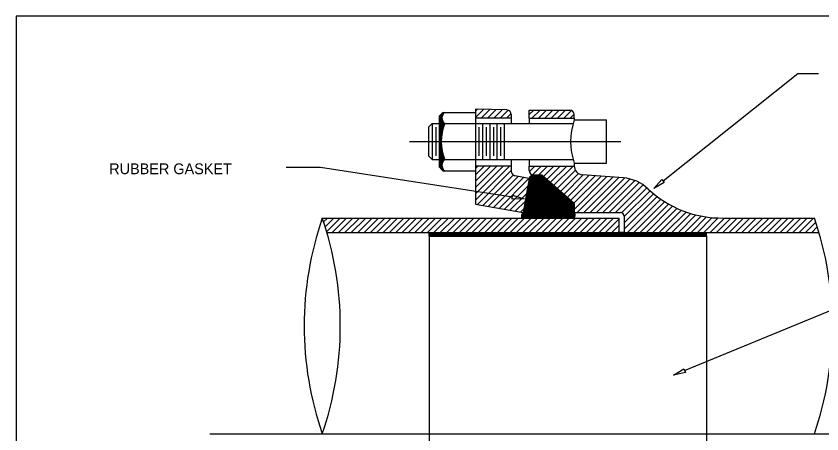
# Model space of a CAD drawing. Extents: x 2147138 to 2147698, y 2147153 to 2147515.
# Drawn here: x 2147558.3 to 2147647.9, y 2147297.7 to 2147344.1 of the extents above; entities that cross this region are included whole.
import ezdxf

# ---------------------------------------------------------------- set-up
doc = ezdxf.new("R2010")
doc.units = 0
for name, color, linetype in [('EQPM', 7, 'Continuous'), ('G-ANNO-TEXT-LW10', 7, 'Continuous'), ('G-DETL-CNTR', 7, 'Continuous'), ('G-DETL-LW10', 7, 'Continuous'), ('G-DETL-PATT', 7, 'Continuous'), ('PATTERN_CLASS', 7, 'Continuous')]:
    doc.layers.add(name, color=color, linetype=linetype)

msp = doc.modelspace()

# ---------------------------------------------------------------- linework, layer by layer
at = {"layer": 'EQPM'}
for p, q in [((2147604.195, 2147319.672), (2147604.195, 2147320.072)), ((2147604.195, 2147320.042), (2147635.045, 2147320.042)), ((2147604.195, 2147319.992), (2147635.045, 2147319.992)), ((2147604.195, 2147319.942), (2147635.045, 2147319.942)), ((2147604.195, 2147319.892), (2147635.045, 2147319.892)), ((2147604.195, 2147319.842), (2147635.045, 2147319.842)), ((2147604.195, 2147319.792), (2147635.045, 2147319.792)), ((2147604.195, 2147319.742), (2147635.045, 2147319.742)), ((2147604.195, 2147319.692), (2147635.045, 2147319.692)), ((2147604.195, 2147319.672), (2147635.045, 2147319.672)), ((2147625.93, 2147320.072), (2147625.33, 2147320.072)), ((2147635.045, 2147319.672), (2147635.045, 2147320.072))]:
    msp.add_line(p, q, dxfattribs=at)
at = {"layer": 'G-ANNO-TEXT-LW10'}
for p, q in [((2147630.207, 2147325.797), (2147645.187, 2147337.726)), ((2147645.187, 2147337.726), (2147647.51, 2147337.726)), ((2147592.12, 2147327.285), (2147588.288, 2147327.285)), ((2147613.444, 2147324.007), (2147592.12, 2147327.285)), ((2147632.604, 2147304.708), (2147649.105, 2147311.508))]:
    msp.add_line(p, q, dxfattribs=at)
for points in [[(2147630.346, 2147325.623), (2147629.163, 2147324.965), (2147630.069, 2147325.971)], [(2147613.478, 2147324.227), (2147614.764, 2147323.805), (2147613.41, 2147323.788)], [(2147632.688, 2147304.502), (2147631.369, 2147304.199), (2147632.519, 2147304.914)]]:
    msp.add_lwpolyline(points, close=True, dxfattribs=at)
at = {"layer": 'G-DETL-CNTR'}
for p, q in [((2147601.998, 2147330.172), (2147625.503, 2147330.172)), ((2147579.795, 2147297.672), (2147660.381, 2147297.672))]:
    msp.add_line(p, q, dxfattribs=at)
at = {"layer": 'G-DETL-LW10'}
for p, q in [((2147605.33, 2147333.022), (2147605.73, 2147333.422)), ((2147605.73, 2147333.422), (2147609.33, 2147333.422)), ((2147612.845, 2147333.687), (2147609.33, 2147333.792)), ((2147609.33, 2147333.792), (2147609.33, 2147332.772)), ((2147609.33, 2147333.422), (2147609.33, 2147326.922)), ((2147613.33, 2147333.187), (2147613.33, 2147332.772)), ((2147615.33, 2147333.672), (2147619.83, 2147333.672)), ((2147615.33, 2147332.772), (2147615.33, 2147333.672)), ((2147620.33, 2147332.772), (2147620.33, 2147333.172)), ((2147605.33, 2147333.022), (2147605.33, 2147327.322)), ((2147613.33, 2147332.772), (2147609.33, 2147332.772)), ((2147613.33, 2147332.772), (2147613.33, 2147332.172)), ((2147615.33, 2147332.772), (2147620.33, 2147332.772)), ((2147615.33, 2147332.772), (2147615.33, 2147332.172)), ((2147620.33, 2147332.772), (2147620.33, 2147332.572)), ((2147620.33, 2147332.572), (2147623.93, 2147332.572)), ((2147623.93, 2147327.772), (2147623.93, 2147332.572)), ((2147604.53, 2147332.172), (2147604.13, 2147331.772)), ((2147604.13, 2147331.772), (2147604.13, 2147328.572)), ((2147604.53, 2147332.172), (2147604.53, 2147328.172)), ((2147604.53, 2147332.172), (2147605.33, 2147332.172)), ((2147604.93, 2147331.772), (2147604.93, 2147328.572)), ((2147605.93, 2147332.172), (2147609.33, 2147332.172)), ((2147609.33, 2147332.172), (2147620.206, 2147332.172)), ((2147609.73, 2147331.772), (2147609.73, 2147328.572)), ((2147610.13, 2147332.172), (2147610.13, 2147328.172)), ((2147610.53, 2147331.772), (2147610.53, 2147328.572)), ((2147610.93, 2147332.172), (2147610.93, 2147328.172)), ((2147611.33, 2147331.772), (2147611.33, 2147328.572)), ((2147611.73, 2147332.172), (2147611.73, 2147328.172)), ((2147612.13, 2147331.772), (2147612.13, 2147328.572)), ((2147612.53, 2147332.172), (2147612.53, 2147328.172)), ((2147604.13, 2147328.572), (2147604.53, 2147328.172)), ((2147604.53, 2147328.172), (2147605.33, 2147328.172)), ((2147605.93, 2147328.172), (2147609.33, 2147328.172)), ((2147609.33, 2147328.172), (2147620.206, 2147328.172)), ((2147613.33, 2147328.172), (2147613.33, 2147327.452)), ((2147615.33, 2147328.052), (2147615.33, 2147327.452)), ((2147620.33, 2147327.772), (2147623.93, 2147327.772)), ((2147620.33, 2147327.772), (2147620.33, 2147327.477)), ((2147605.33, 2147327.322), (2147605.73, 2147326.922)), ((2147605.73, 2147326.922), (2147609.33, 2147326.922)), ((2147609.33, 2147327.452), (2147609.33, 2147323.21)), ((2147613.33, 2147327.452), (2147609.33, 2147327.452)), ((2147613.33, 2147327.452), (2147613.33, 2147326.862)), ((2147615.33, 2147327.452), (2147620.33, 2147327.452)), ((2147615.33, 2147326.952), (2147615.33, 2147327.452)), ((2147615.33, 2147326.052), (2147613.732, 2147326.372)), ((2147615.33, 2147326.052), (2147614.663, 2147322.27)), ((2147615.357, 2147326.069), (2147614.671, 2147322.245)), ((2147615.334, 2147326.18), (2147615.314, 2147326.12)), ((2147615.314, 2147326.12), (2147615.314, 2147326.077)), ((2147615.314, 2147326.077), (2147615.357, 2147326.069)), ((2147615.373, 2147326.247), (2147615.334, 2147326.18)), ((2147615.456, 2147326.318), (2147615.373, 2147326.247)), ((2147615.559, 2147326.381), (2147615.456, 2147326.318)), ((2147615.642, 2147326.417), (2147615.559, 2147326.381)), ((2147615.717, 2147326.437), (2147615.642, 2147326.417)), ((2147616.725, 2147326.438), (2147615.717, 2147326.437)), ((2147615.83, 2147326.452), (2147616.73, 2147326.452)), ((2147620.305, 2147323.261), (2147616.725, 2147326.438)), ((2147620.33, 2147323.272), (2147616.73, 2147326.452)), ((2147625.793, 2147326.138), (2147621.252, 2147326.48)), ((2147620.304, 2147322.261), (2147620.305, 2147323.261)), ((2147620.33, 2147323.272), (2147620.33, 2147322.272)), ((2147609.33, 2147323.21), (2147614.663, 2147322.27)), ((2147592.302, 2147321.672), (2147625.33, 2147321.672)), ((2147614.466, 2147321.878), (2147614.459, 2147321.824)), ((2147614.459, 2147321.824), (2147614.459, 2147321.786)), ((2147614.459, 2147321.786), (2147614.464, 2147321.764)), ((2147614.464, 2147321.764), (2147614.478, 2147321.751)), ((2147614.479, 2147321.985), (2147614.466, 2147321.878)), ((2147614.478, 2147321.751), (2147614.498, 2147321.748)), ((2147614.504, 2147322.066), (2147614.479, 2147321.985)), ((2147614.498, 2147321.748), (2147614.519, 2147321.747)), ((2147614.539, 2147322.143), (2147614.504, 2147322.066)), ((2147614.519, 2147321.747), (2147620.341, 2147321.747)), ((2147614.59, 2147322.202), (2147614.539, 2147322.143)), ((2147614.628, 2147322.232), (2147614.59, 2147322.202)), ((2147614.671, 2147322.245), (2147614.628, 2147322.232)), ((2147620.39, 2147322.165), (2147620.304, 2147322.261)), ((2147620.33, 2147322.272), (2147625.43, 2147322.272)), ((2147620.341, 2147321.747), (2147620.395, 2147321.825)), ((2147620.422, 2147322.084), (2147620.39, 2147322.165)), ((2147620.395, 2147321.825), (2147620.431, 2147321.956)), ((2147620.431, 2147321.956), (2147620.422, 2147322.084)), ((2147625.33, 2147320.072), (2147625.33, 2147321.672)), ((2147625.93, 2147320.072), (2147625.93, 2147321.772)), ((2147636.86, 2147321.672), (2147647.038, 2147321.672)), ((2147592.813, 2147320.072), (2147625.33, 2147320.072)), ((2147625.93, 2147320.072), (2147647.548, 2147320.072))]:
    msp.add_line(p, q, dxfattribs=at)
for centre, radius, start, end in [((2147606.401, 2147332.797), 0.783, 127.00306, 232.99694), ((2147612.83, 2147333.187), 0.5, 0, 88.28164), ((2147619.83, 2147333.172), 0.5, 0, 90), ((2147627.33, 2147330.172), 7.4, 161.07536, 198.92464), ((2147610.73, 2147330.172), 5.2, 157.38014, 202.61986), ((2147606.401, 2147327.547), 0.783, 127.00306, 232.99694), ((2147613.83, 2147326.862), 0.5, 180, 258.69007), ((2147615.83, 2147326.952), 0.5, 180, 270), ((2147621.33, 2147327.477), 1, 180, 265.5072), ((2147625.43, 2147321.652), 4.5, 46.15465, 85.38171), ((2147636.69, 2147333.558), 11.886, 226.76421, 270.82117), ((2147627.142, 2147309.672), 36.849, 160.99467, 199.00533), ((2147627.142, 2147309.672), 36.849, 160.99467, 199.00533), ((2147557.462, 2147309.672), 36.849, 340.99467, 19.00533), ((2147625.43, 2147321.772), 0.5, 0, 90), ((2147612.198, 2147309.672), 36.849, 340.99467, 19.00533)]:
    msp.add_arc(centre, radius, start, end, dxfattribs=at)
at = {"layer": 'G-DETL-PATT'}
for p, q in [((2147605.45, 2147330.172), (2147605.45, 2147333.142)), ((2147605.5, 2147330.172), (2147605.5, 2147333.192)), ((2147605.55, 2147330.625), (2147605.55, 2147333.242)), ((2147605.6, 2147331.021), (2147605.6, 2147333.292)), ((2147605.65, 2147333.017), (2147605.65, 2147333.342)), ((2147605.7, 2147333.145), (2147605.7, 2147333.392)), ((2147605.75, 2147333.231), (2147605.75, 2147333.422)), ((2147605.8, 2147333.298), (2147605.8, 2147333.422)), ((2147605.85, 2147333.353), (2147605.85, 2147333.422)), ((2147605.9, 2147333.398), (2147605.9, 2147333.422)), ((2147609.33, 2147333.546), (2147609.569, 2147333.785)), ((2147609.33, 2147332.839), (2147610.256, 2147333.765)), ((2147609.971, 2147332.772), (2147610.942, 2147333.744)), ((2147610.678, 2147332.772), (2147611.629, 2147333.723)), ((2147611.385, 2147332.772), (2147612.315, 2147333.703)), ((2147612.092, 2147332.772), (2147612.983, 2147333.663)), ((2147612.799, 2147332.772), (2147613.319, 2147333.292)), ((2147615.33, 2147333.182), (2147615.82, 2147333.672)), ((2147615.627, 2147332.772), (2147616.527, 2147333.672)), ((2147616.335, 2147332.772), (2147617.235, 2147333.672)), ((2147617.042, 2147332.772), (2147617.942, 2147333.672)), ((2147617.749, 2147332.772), (2147618.649, 2147333.672)), ((2147618.456, 2147332.772), (2147619.356, 2147333.672)), ((2147619.163, 2147332.772), (2147620.024, 2147333.633)), ((2147619.87, 2147332.772), (2147620.327, 2147333.229)), ((2147605.35, 2147330.172), (2147605.35, 2147333.042)), ((2147605.4, 2147330.172), (2147605.4, 2147333.092)), ((2147605.65, 2147331.282), (2147605.65, 2147332.578)), ((2147605.7, 2147331.49), (2147605.7, 2147332.45)), ((2147605.75, 2147331.668), (2147605.75, 2147332.363)), ((2147605.8, 2147331.825), (2147605.8, 2147332.296)), ((2147605.85, 2147331.968), (2147605.85, 2147332.242)), ((2147605.9, 2147332.098), (2147605.9, 2147332.196)), ((2147605.35, 2147327.303), (2147605.35, 2147330.172)), ((2147605.4, 2147327.253), (2147605.4, 2147330.172)), ((2147605.45, 2147327.203), (2147605.45, 2147330.172)), ((2147605.5, 2147327.153), (2147605.5, 2147330.172)), ((2147605.55, 2147327.103), (2147605.55, 2147329.72)), ((2147605.6, 2147327.053), (2147605.6, 2147329.324)), ((2147605.65, 2147327.767), (2147605.65, 2147329.063)), ((2147605.7, 2147327.895), (2147605.7, 2147328.855)), ((2147605.75, 2147327.981), (2147605.75, 2147328.677)), ((2147605.8, 2147328.048), (2147605.8, 2147328.519)), ((2147605.85, 2147328.103), (2147605.85, 2147328.377)), ((2147605.9, 2147328.148), (2147605.9, 2147328.247)), ((2147605.65, 2147327.003), (2147605.65, 2147327.328)), ((2147605.7, 2147326.953), (2147605.7, 2147327.2)), ((2147605.75, 2147326.922), (2147605.75, 2147327.113)), ((2147605.8, 2147326.922), (2147605.8, 2147327.046)), ((2147605.85, 2147326.922), (2147605.85, 2147326.992)), ((2147605.9, 2147326.922), (2147605.9, 2147326.946)), ((2147609.33, 2147327.182), (2147609.6, 2147327.452)), ((2147609.33, 2147326.475), (2147610.307, 2147327.452)), ((2147609.33, 2147325.768), (2147611.015, 2147327.452)), ((2147609.33, 2147325.061), (2147611.722, 2147327.452)), ((2147609.33, 2147324.354), (2147612.429, 2147327.452)), ((2147609.33, 2147323.647), (2147613.136, 2147327.452)), ((2147609.56, 2147323.17), (2147613.33, 2147326.94)), ((2147615.342, 2147326.843), (2147615.952, 2147327.452)), ((2147615.682, 2147326.475), (2147616.659, 2147327.452)), ((2147616.366, 2147326.452), (2147617.366, 2147327.452)), ((2147616.912, 2147326.292), (2147618.073, 2147327.452)), ((2147617.288, 2147325.96), (2147618.78, 2147327.452)), ((2147617.663, 2147325.628), (2147619.488, 2147327.452)), ((2147618.039, 2147325.297), (2147620.195, 2147327.452)), ((2147618.414, 2147324.965), (2147620.451, 2147327.001)), ((2147610.161, 2147323.064), (2147613.548, 2147326.45)), ((2147610.762, 2147322.958), (2147614.103, 2147326.298)), ((2147611.363, 2147322.852), (2147614.692, 2147326.18)), ((2147611.965, 2147322.746), (2147615.281, 2147326.062)), ((2147615.375, 2147321.747), (2147615.375, 2147326.249)), ((2147615.5, 2147321.747), (2147615.5, 2147326.345)), ((2147615.625, 2147321.747), (2147615.625, 2147326.41)), ((2147615.75, 2147321.747), (2147615.75, 2147326.437)), ((2147615.875, 2147321.747), (2147615.875, 2147326.437)), ((2147616, 2147321.747), (2147616, 2147326.437)), ((2147616.125, 2147321.747), (2147616.125, 2147326.437)), ((2147616.25, 2147321.747), (2147616.25, 2147326.437)), ((2147616.375, 2147321.747), (2147616.375, 2147326.437)), ((2147616.5, 2147321.747), (2147616.5, 2147326.437)), ((2147616.625, 2147321.747), (2147616.625, 2147326.437)), ((2147616.75, 2147321.747), (2147616.75, 2147326.416)), ((2147616.875, 2147321.747), (2147616.875, 2147326.305)), ((2147617, 2147321.747), (2147617, 2147326.194)), ((2147617.125, 2147321.747), (2147617.125, 2147326.083)), ((2147617.25, 2147321.747), (2147617.25, 2147325.972)), ((2147618.79, 2147324.633), (2147620.791, 2147326.635)), ((2147619.165, 2147324.302), (2147621.337, 2147326.474)), ((2147619.541, 2147323.97), (2147621.995, 2147326.424)), ((2147619.916, 2147323.638), (2147622.652, 2147326.374)), ((2147620.292, 2147323.307), (2147623.31, 2147326.325)), ((2147620.33, 2147322.638), (2147623.967, 2147326.275)), ((2147620.671, 2147322.272), (2147624.625, 2147326.226)), ((2147621.379, 2147322.272), (2147625.282, 2147326.176)), ((2147622.086, 2147322.272), (2147625.937, 2147326.124)), ((2147622.793, 2147322.272), (2147626.535, 2147326.015)), ((2147612.566, 2147322.64), (2147615.191, 2147325.265)), ((2147615.25, 2147321.747), (2147615.25, 2147325.471)), ((2147617.375, 2147321.747), (2147617.375, 2147325.861)), ((2147617.5, 2147321.747), (2147617.5, 2147325.75)), ((2147617.625, 2147321.747), (2147617.625, 2147325.639)), ((2147617.75, 2147321.747), (2147617.75, 2147325.528)), ((2147617.875, 2147321.747), (2147617.875, 2147325.417)), ((2147618, 2147321.747), (2147618, 2147325.306)), ((2147618.125, 2147321.747), (2147618.125, 2147325.196)), ((2147618.25, 2147321.747), (2147618.25, 2147325.085)), ((2147623.5, 2147322.272), (2147627.07, 2147325.843)), ((2147624.207, 2147322.272), (2147627.554, 2147325.62)), ((2147624.914, 2147322.272), (2147627.993, 2147325.351)), ((2147613.167, 2147322.534), (2147615.04, 2147324.407)), ((2147615.125, 2147321.747), (2147615.125, 2147324.775)), ((2147618.375, 2147321.747), (2147618.375, 2147324.974)), ((2147618.5, 2147321.747), (2147618.5, 2147324.863)), ((2147618.625, 2147321.747), (2147618.625, 2147324.752)), ((2147618.75, 2147321.747), (2147618.75, 2147324.641)), ((2147618.875, 2147321.747), (2147618.875, 2147324.53)), ((2147619, 2147321.747), (2147619, 2147324.419)), ((2147619.125, 2147321.747), (2147619.125, 2147324.308)), ((2147619.25, 2147321.747), (2147619.25, 2147324.197)), ((2147625.594, 2147322.245), (2147628.39, 2147325.042)), ((2147625.922, 2147321.866), (2147628.759, 2147324.703)), ((2147625.93, 2147321.167), (2147629.14, 2147324.377)), ((2147613.768, 2147322.428), (2147614.889, 2147323.548)), ((2147614.875, 2147321.747), (2147614.875, 2147323.382)), ((2147615, 2147321.747), (2147615, 2147324.078)), ((2147619.375, 2147321.747), (2147619.375, 2147324.086)), ((2147619.5, 2147321.747), (2147619.5, 2147323.975)), ((2147619.625, 2147321.747), (2147619.625, 2147323.864)), ((2147619.75, 2147321.747), (2147619.75, 2147323.754)), ((2147619.875, 2147321.747), (2147619.875, 2147323.643)), ((2147620, 2147321.747), (2147620, 2147323.532)), ((2147620.125, 2147321.747), (2147620.125, 2147323.421)), ((2147620.25, 2147321.747), (2147620.25, 2147323.31)), ((2147625.93, 2147320.46), (2147629.535, 2147324.065)), ((2147626.25, 2147320.072), (2147629.946, 2147323.769)), ((2147626.957, 2147320.072), (2147630.373, 2147323.489)), ((2147614.369, 2147322.322), (2147614.737, 2147322.69)), ((2147614.75, 2147321.747), (2147614.75, 2147322.685)), ((2147627.664, 2147320.072), (2147630.816, 2147323.224)), ((2147628.371, 2147320.072), (2147631.275, 2147322.976)), ((2147629.078, 2147320.072), (2147631.751, 2147322.746)), ((2147629.785, 2147320.072), (2147632.246, 2147322.533)), ((2147592.451, 2147321.232), (2147592.891, 2147321.672)), ((2147592.623, 2147320.697), (2147593.599, 2147321.672)), ((2147592.788, 2147320.155), (2147594.306, 2147321.672)), ((2147593.413, 2147320.072), (2147595.013, 2147321.672)), ((2147594.12, 2147320.072), (2147595.72, 2147321.672)), ((2147594.827, 2147320.072), (2147596.427, 2147321.672)), ((2147595.534, 2147320.072), (2147597.134, 2147321.672)), ((2147596.241, 2147320.072), (2147597.841, 2147321.672)), ((2147596.948, 2147320.072), (2147598.548, 2147321.672)), ((2147597.655, 2147320.072), (2147599.255, 2147321.672)), ((2147598.363, 2147320.072), (2147599.963, 2147321.672)), ((2147599.07, 2147320.072), (2147600.67, 2147321.672)), ((2147599.777, 2147320.072), (2147601.377, 2147321.672)), ((2147600.484, 2147320.072), (2147602.084, 2147321.672)), ((2147601.191, 2147320.072), (2147602.791, 2147321.672)), ((2147601.898, 2147320.072), (2147603.498, 2147321.672)), ((2147602.605, 2147320.072), (2147604.205, 2147321.672)), ((2147603.312, 2147320.072), (2147604.912, 2147321.672)), ((2147604.019, 2147320.072), (2147605.619, 2147321.672)), ((2147604.727, 2147320.072), (2147606.327, 2147321.672)), ((2147605.434, 2147320.072), (2147607.034, 2147321.672)), ((2147606.141, 2147320.072), (2147607.741, 2147321.672)), ((2147606.848, 2147320.072), (2147608.448, 2147321.672)), ((2147607.555, 2147320.072), (2147609.155, 2147321.672)), ((2147608.262, 2147320.072), (2147609.862, 2147321.672)), ((2147608.969, 2147320.072), (2147610.569, 2147321.672)), ((2147609.676, 2147320.072), (2147611.276, 2147321.672)), ((2147610.383, 2147320.072), (2147611.983, 2147321.672)), ((2147611.09, 2147320.072), (2147612.69, 2147321.672)), ((2147611.798, 2147320.072), (2147613.398, 2147321.672)), ((2147612.505, 2147320.072), (2147614.105, 2147321.672)), ((2147613.212, 2147320.072), (2147614.812, 2147321.672)), ((2147613.919, 2147320.072), (2147615.519, 2147321.672)), ((2147614.5, 2147321.747), (2147614.5, 2147322.052)), ((2147614.625, 2147321.747), (2147614.625, 2147322.23)), ((2147614.626, 2147320.072), (2147616.226, 2147321.672)), ((2147615.333, 2147320.072), (2147616.933, 2147321.672)), ((2147616.04, 2147320.072), (2147617.64, 2147321.672)), ((2147616.747, 2147320.072), (2147618.347, 2147321.672)), ((2147617.454, 2147320.072), (2147619.054, 2147321.672)), ((2147618.162, 2147320.072), (2147619.762, 2147321.672)), ((2147618.869, 2147320.072), (2147620.469, 2147321.672)), ((2147619.576, 2147320.072), (2147621.176, 2147321.672)), ((2147620.283, 2147320.072), (2147621.883, 2147321.672)), ((2147620.375, 2147321.796), (2147620.375, 2147322.182)), ((2147620.99, 2147320.072), (2147622.59, 2147321.672)), ((2147621.697, 2147320.072), (2147623.297, 2147321.672)), ((2147622.404, 2147320.072), (2147624.004, 2147321.672)), ((2147623.111, 2147320.072), (2147624.711, 2147321.672)), ((2147623.818, 2147320.072), (2147625.33, 2147321.584)), ((2147630.492, 2147320.072), (2147632.76, 2147322.34)), ((2147631.199, 2147320.072), (2147633.294, 2147322.167)), ((2147631.907, 2147320.072), (2147633.85, 2147322.015)), ((2147632.614, 2147320.072), (2147634.429, 2147321.888)), ((2147633.321, 2147320.072), (2147635.035, 2147321.787)), ((2147634.028, 2147320.072), (2147635.67, 2147321.715)), ((2147634.735, 2147320.072), (2147636.339, 2147321.676)), ((2147635.442, 2147320.072), (2147637.042, 2147321.672)), ((2147636.149, 2147320.072), (2147637.749, 2147321.672)), ((2147636.856, 2147320.072), (2147638.456, 2147321.672)), ((2147637.563, 2147320.072), (2147639.163, 2147321.672)), ((2147638.27, 2147320.072), (2147639.87, 2147321.672)), ((2147638.978, 2147320.072), (2147640.578, 2147321.672)), ((2147639.685, 2147320.072), (2147641.285, 2147321.672)), ((2147640.392, 2147320.072), (2147641.992, 2147321.672)), ((2147641.099, 2147320.072), (2147642.699, 2147321.672)), ((2147641.806, 2147320.072), (2147643.406, 2147321.672)), ((2147642.513, 2147320.072), (2147644.113, 2147321.672)), ((2147643.22, 2147320.072), (2147644.82, 2147321.672)), ((2147643.927, 2147320.072), (2147645.527, 2147321.672)), ((2147644.634, 2147320.072), (2147646.234, 2147321.672)), ((2147645.342, 2147320.072), (2147646.942, 2147321.672)), ((2147624.525, 2147320.072), (2147625.33, 2147320.877)), ((2147646.049, 2147320.072), (2147647.192, 2147321.216)), ((2147646.756, 2147320.072), (2147647.364, 2147320.68)), ((2147604.195, 2147319.672), (2147604.195, 2147275.672)), ((2147625.233, 2147320.072), (2147625.33, 2147320.17)), ((2147635.045, 2147319.672), (2147635.045, 2147275.653)), ((2147647.463, 2147320.072), (2147647.529, 2147320.138))]:
    msp.add_line(p, q, dxfattribs=at)
at = {"layer": 'PATTERN_CLASS'}
for p, q in [((2147682.438, 2147344.122), (2147558.253, 2147344.122)), ((2147558.253, 2147344.122), (2147558.253, 2147215.016))]:
    msp.add_line(p, q, dxfattribs=at)

# ---------------------------------------------------------------- texts
at = {"layer": 'G-ANNO-TEXT-LW10'}
msp.add_text('RUBBER GASKET', height=1.2, dxfattribs=at).set_placement((2147568.608, 2147326.547))

doc.saveas('drawing.dxf')
